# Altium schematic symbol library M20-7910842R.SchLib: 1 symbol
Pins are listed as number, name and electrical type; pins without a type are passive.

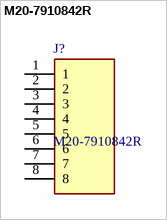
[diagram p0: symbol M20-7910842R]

## M20-7910842R
designator J?
2.54mm (0.1") Pitch SIL Horizontal SMT Socket Assembly, selective gold + tin (Tape & Reel packing), 8 contacts; Manufacturer_Name: Harwin; Geometry.Height: 2.65mm
footprint M207910842R
pins: 1, 2, 3, 4, 5, 6, 7, 8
